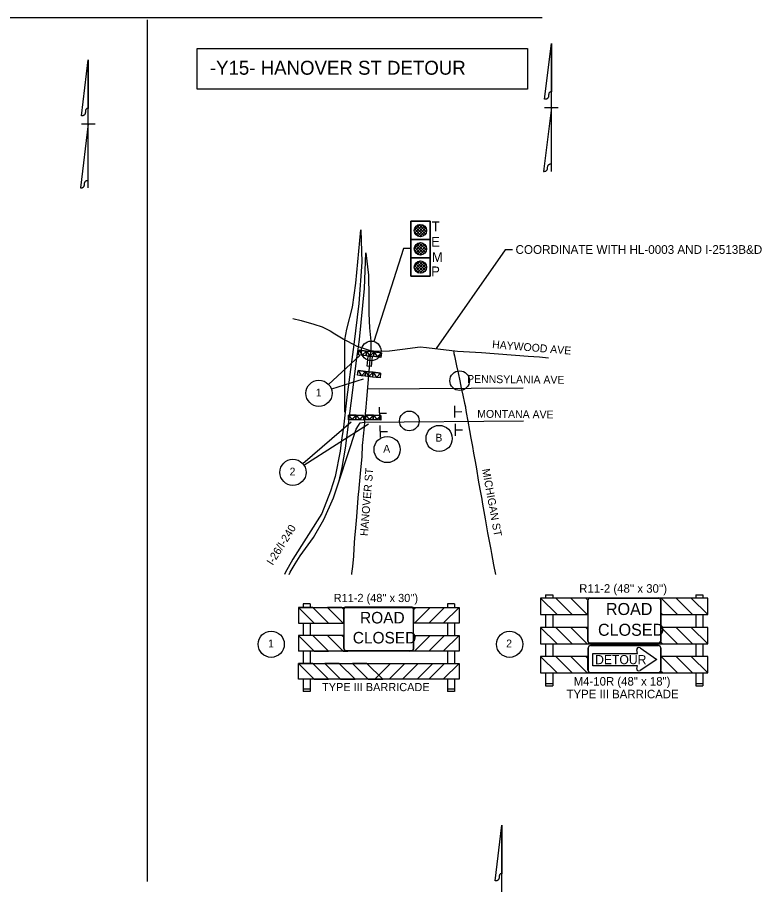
# Model space of a CAD drawing. Extents: x 886234 to 968767, y 455416 to 684046.
# Drawn here: x 915519 to 926197, y 535743 to 548185 of the extents above; entities that cross this region are included whole.
import ezdxf

# ---------------------------------------------------------------- set-up
doc = ezdxf.new("R2010")
doc.units = 0
for name, color, linetype in [('Scratch_Level_3', 7, 'Continuous'), ('TC CONSTRUCTION PROPOSED ROADWAY SHADE', 7, 'Continuous'), ('TC DEV BARRICADE', 7, 'Continuous'), ('TC DEV SIGN', 7, 'Continuous'), ('TC DEV SIGN BLACK 239', 7, 'Continuous'), ('TC DEV SIGN BLACK ZERO', 7, 'Continuous'), ('TC DEV SIGN ORANGE', 7, 'Continuous'), ('TC DEV SIGN WHITE', 7, 'Continuous'), ('TC DEV SIGNAL', 7, 'Continuous'), ('TC LABEL TEXT', 7, 'Continuous'), ('TC SHEET LAYOUT SHAPE', 7, 'Continuous')]:
    doc.layers.add(name, color=color, linetype=linetype)

msp = doc.modelspace()

# ---------------------------------------------------------------- linework, layer by layer
at = {"layer": 'Scratch_Level_3'}
msp.add_line((904674, 548185), (923047, 548185), dxfattribs=at)
at = {"layer": 'TC CONSTRUCTION PROPOSED ROADWAY SHADE'}
msp.add_lwpolyline([(920538, 543179), (920551, 543323), (920607, 543318), (920595, 543176)], close=True, dxfattribs=at)
at = {"layer": 'TC DEV BARRICADE'}
for p, q in [((920413, 543343), (920421, 543410)), ((920421, 543410), (920468, 543337)), ((920468, 543337), (920528, 543398)), ((920528, 543398), (920521, 543331)), ((920521, 543331), (920528, 543398)), ((920528, 543398), (920575, 543325)), ((920575, 543325), (920636, 543386)), ((920636, 543386), (920628, 543319)), ((920628, 543319), (920636, 543386)), ((920636, 543386), (920683, 543313)), ((920683, 543313), (920743, 543374)), ((920743, 543374), (920735, 543307)), ((920468, 543337), (920413, 543343)), ((920521, 543331), (920468, 543337)), ((920468, 543337), (920468, 543337)), ((920468, 543337), (920468, 543337)), ((920575, 543325), (920521, 543331)), ((920628, 543319), (920575, 543325)), ((920575, 543325), (920575, 543325)), ((920575, 543325), (920575, 543325)), ((920683, 543313), (920628, 543319)), ((920735, 543307), (920683, 543313)), ((920683, 543313), (920683, 543313)), ((920683, 543313), (920683, 543313)), ((920400, 543050), (920407, 543117)), ((920407, 543117), (920454, 543043)), ((920454, 543043), (920514, 543105)), ((920514, 543105), (920507, 543037)), ((920507, 543037), (920514, 543105)), ((920514, 543105), (920561, 543031)), ((920454, 543043), (920400, 543050)), ((920507, 543037), (920454, 543043)), ((920454, 543043), (920454, 543043)), ((920454, 543043), (920454, 543043)), ((920561, 543031), (920507, 543037)), ((920561, 543031), (920622, 543093)), ((920614, 543025), (920561, 543031)), ((920561, 543031), (920561, 543031)), ((920561, 543031), (920561, 543031)), ((920622, 543093), (920614, 543025)), ((920614, 543025), (920622, 543093)), ((920669, 543019), (920614, 543025)), ((920622, 543093), (920669, 543019)), ((920669, 543019), (920729, 543081)), ((920722, 543013), (920669, 543019)), ((920669, 543019), (920669, 543019)), ((920669, 543019), (920669, 543019)), ((920729, 543081), (920722, 543013)), ((920268, 542412), (920270, 542480)), ((920323, 542411), (920268, 542412)), ((920270, 542480), (920323, 542411)), ((920323, 542411), (920378, 542477)), ((920376, 542410), (920323, 542411)), ((920323, 542411), (920323, 542411)), ((920323, 542411), (920323, 542411)), ((920378, 542477), (920376, 542410)), ((920376, 542410), (920378, 542477)), ((920431, 542409), (920376, 542410)), ((920378, 542477), (920431, 542409)), ((920431, 542409), (920486, 542475)), ((920484, 542407), (920431, 542409)), ((920431, 542409), (920431, 542409)), ((920431, 542409), (920431, 542409)), ((920486, 542475), (920484, 542407)), ((920517, 542413), (920519, 542480)), ((920572, 542411), (920517, 542413)), ((920519, 542480), (920572, 542411)), ((920572, 542411), (920627, 542478)), ((920625, 542410), (920572, 542411)), ((920572, 542411), (920572, 542411)), ((920572, 542411), (920572, 542411)), ((920627, 542478), (920625, 542410)), ((920625, 542410), (920627, 542478)), ((920680, 542409), (920625, 542410)), ((920627, 542478), (920680, 542409)), ((920680, 542409), (920735, 542475)), ((920733, 542408), (920680, 542409)), ((920680, 542409), (920680, 542409)), ((920680, 542409), (920680, 542409)), ((920735, 542475), (920733, 542408)), ((923097, 539903), (923199, 539903)), ((923097, 539903), (923097, 539852)), ((923199, 539903), (923199, 539852)), ((925252, 539903), (925354, 539903)), ((925252, 539903), (925252, 539852)), ((925354, 539903), (925354, 539852)), ((919718, 539770), (919621, 539770)), ((919621, 539770), (919621, 539721)), ((919718, 539770), (919718, 539721)), ((921788, 539770), (921690, 539770)), ((921690, 539770), (921690, 539721)), ((921788, 539770), (921788, 539721)), ((923026, 539852), (923026, 539617)), ((923242, 539852), (923026, 539852)), ((923026, 539852), (923261, 539617)), ((925426, 539852), (923026, 539852)), ((923477, 539617), (923242, 539852)), ((923674, 539852), (923458, 539852)), ((923458, 539852), (923693, 539617)), ((923704, 539822), (923674, 539852)), ((923702, 539617), (923702, 539814)), ((924970, 539852), (924754, 539852)), ((924754, 539852), (924990, 539617)), ((925206, 539617), (924970, 539852)), ((925426, 539852), (925186, 539852)), ((925186, 539852), (925426, 539617)), ((925426, 539617), (925426, 539852)), ((925426, 539617), (925426, 539852)), ((919759, 539721), (919552, 539721)), ((919552, 539721), (919778, 539495)), ((919552, 539721), (919552, 539495)), ((919552, 539721), (921856, 539721)), ((919985, 539495), (919759, 539721)), ((920174, 539721), (919967, 539721)), ((919967, 539721), (920193, 539495)), ((920203, 539692), (920174, 539721)), ((920202, 539495), (920202, 539685)), ((921205, 539692), (921234, 539721)), ((921206, 539495), (921206, 539685)), ((921441, 539721), (921216, 539495)), ((921234, 539721), (921441, 539721)), ((921423, 539495), (921649, 539721)), ((921856, 539721), (921630, 539495)), ((921649, 539721), (921856, 539721)), ((921856, 539721), (921856, 539495)), ((924774, 539617), (924749, 539642)), ((924749, 539642), (924749, 539617)), ((919552, 539495), (920202, 539495)), ((919621, 539495), (919621, 539319)), ((919718, 539495), (919718, 539319)), ((919778, 539495), (919985, 539495)), ((920193, 539495), (920202, 539495)), ((921216, 539495), (921206, 539495)), ((921856, 539495), (921206, 539495)), ((921630, 539495), (921423, 539495)), ((921690, 539495), (921690, 539319)), ((921788, 539495), (921788, 539319)), ((923026, 539617), (923702, 539617)), ((923097, 539617), (923097, 539434)), ((923199, 539617), (923199, 539434)), ((923261, 539617), (923477, 539617)), ((923693, 539617), (923702, 539617)), ((924749, 539617), (925426, 539617)), ((924749, 539617), (924774, 539617)), ((924990, 539617), (925206, 539617)), ((925252, 539617), (925252, 539434)), ((925354, 539617), (925354, 539434)), ((923026, 539434), (923026, 539198)), ((923242, 539434), (923026, 539434)), ((923026, 539434), (923261, 539198)), ((923702, 539434), (923026, 539434)), ((923477, 539198), (923242, 539434)), ((923458, 539434), (923693, 539198)), ((923674, 539434), (923458, 539434)), ((923702, 539405), (923674, 539434)), ((923702, 539236), (923702, 539405)), ((925426, 539434), (924749, 539434)), ((924970, 539434), (924754, 539434)), ((924754, 539434), (924990, 539198)), ((925206, 539198), (924970, 539434)), ((925426, 539434), (925186, 539434)), ((925186, 539434), (925426, 539198)), ((925426, 539198), (925426, 539434)), ((925426, 539198), (925426, 539434)), ((919552, 539319), (919552, 539093)), ((919759, 539319), (919552, 539319)), ((919552, 539319), (919778, 539093)), ((920202, 539319), (919552, 539319)), ((919985, 539093), (919759, 539319)), ((919967, 539319), (920193, 539093)), ((920174, 539319), (919967, 539319)), ((920202, 539292), (920174, 539319)), ((920202, 539130), (920202, 539292)), ((921206, 539292), (921234, 539319)), ((921206, 539319), (921856, 539319)), ((921206, 539130), (921206, 539292)), ((921441, 539319), (921216, 539093)), ((921234, 539319), (921441, 539319)), ((921423, 539093), (921649, 539319)), ((921856, 539319), (921630, 539093)), ((921649, 539319), (921856, 539319)), ((921856, 539319), (921856, 539093)), ((923026, 539198), (925426, 539198)), ((923097, 539198), (923097, 539015)), ((923199, 539198), (923199, 539015)), ((923261, 539198), (923477, 539198)), ((923693, 539198), (923763, 539198)), ((924688, 539198), (924774, 539198)), ((924774, 539198), (924746, 539226)), ((924990, 539198), (925206, 539198)), ((925252, 539198), (925252, 539015)), ((925354, 539198), (925354, 539015)), ((921856, 539093), (919552, 539093)), ((919621, 539093), (919621, 538917)), ((919718, 539093), (919718, 538917)), ((919778, 539093), (919985, 539093)), ((920193, 539093), (920260, 539093)), ((921216, 539093), (921148, 539093)), ((921630, 539093), (921423, 539093)), ((921690, 539093), (921690, 538917)), ((921788, 539093), (921788, 538917)), ((923026, 539015), (923026, 538780)), ((923242, 539015), (923026, 539015)), ((923026, 539015), (923261, 538780)), ((923702, 539015), (923026, 539015)), ((923477, 538780), (923242, 539015)), ((923458, 539015), (923693, 538780)), ((923674, 539015), (923458, 539015)), ((923702, 538986), (923674, 539015)), ((925426, 539015), (924749, 539015)), ((924970, 539015), (924754, 539015)), ((924754, 539015), (924990, 538780)), ((925206, 538780), (924970, 539015)), ((925426, 539015), (925186, 539015)), ((925186, 539015), (925426, 538780)), ((925426, 538780), (925426, 539015)), ((925426, 538780), (925426, 539015)), ((919759, 538917), (919552, 538917)), ((919552, 538917), (919778, 538692)), ((919985, 538692), (919759, 538917)), ((920137, 538917), (919929, 538917)), ((919929, 538917), (920155, 538692)), ((920363, 538691), (920137, 538917)), ((920535, 538917), (920328, 538917)), ((920328, 538917), (920554, 538692)), ((920761, 538692), (920535, 538917)), ((920647, 538692), (920873, 538917)), ((921080, 538917), (920854, 538692)), ((920873, 538917), (921080, 538917)), ((921046, 538691), (921271, 538917)), ((921479, 538917), (921253, 538692)), ((921271, 538917), (921479, 538917)), ((921423, 538692), (921649, 538917)), ((921856, 538917), (921630, 538692)), ((921649, 538917), (921856, 538917)), ((923702, 538818), (923702, 538986)), ((923026, 538780), (925426, 538780)), ((923097, 538780), (923097, 538596)), ((923199, 538780), (923199, 538596)), ((923261, 538780), (923477, 538780)), ((923693, 538780), (923763, 538780)), ((924688, 538780), (924774, 538780)), ((924774, 538780), (924746, 538807)), ((924990, 538780), (925206, 538780)), ((925252, 538780), (925252, 538596)), ((925354, 538780), (925354, 538596)), ((919621, 538692), (919621, 538515)), ((919718, 538692), (919718, 538515)), ((919778, 538692), (919985, 538692)), ((920155, 538692), (920363, 538691)), ((920554, 538692), (920761, 538692)), ((920854, 538692), (920647, 538692)), ((921253, 538692), (921046, 538691)), ((921630, 538692), (921423, 538692)), ((921690, 538692), (921690, 538515)), ((921788, 538692), (921788, 538515)), ((923097, 538627), (923199, 538627)), ((925252, 538627), (925354, 538627)), ((919718, 538545), (919621, 538545)), ((919718, 538515), (919621, 538515)), ((921788, 538545), (921690, 538545)), ((921788, 538515), (921690, 538515)), ((923097, 538596), (923199, 538596)), ((925252, 538596), (925354, 538596))]:
    msp.add_line(p, q, dxfattribs=at)
for points in [[(920413, 543343), (920421, 543410), (920528, 543398), (920521, 543331)], [(920421, 543410), (920468, 543337), (920528, 543398)], [(920521, 543331), (920528, 543398), (920636, 543386), (920628, 543319)], [(920528, 543398), (920575, 543325), (920636, 543386)], [(920628, 543319), (920636, 543386), (920743, 543374), (920735, 543307)], [(920636, 543386), (920683, 543313), (920743, 543374)], [(920400, 543050), (920407, 543117), (920514, 543105), (920507, 543037)], [(920407, 543117), (920454, 543043), (920514, 543105)], [(920507, 543037), (920514, 543105), (920622, 543093), (920614, 543025)], [(920514, 543105), (920561, 543031), (920622, 543093)], [(920614, 543025), (920622, 543093), (920729, 543081), (920722, 543013)], [(920622, 543093), (920669, 543019), (920729, 543081)], [(920268, 542412), (920270, 542480), (920378, 542477), (920376, 542410)], [(920270, 542480), (920323, 542411), (920378, 542477)], [(920376, 542410), (920378, 542477), (920486, 542475), (920484, 542407)], [(920378, 542477), (920431, 542409), (920486, 542475)], [(920517, 542413), (920519, 542480), (920627, 542478), (920625, 542410)], [(920519, 542480), (920572, 542411), (920627, 542478)], [(920625, 542410), (920627, 542478), (920735, 542475), (920733, 542408)], [(920627, 542478), (920680, 542409), (920735, 542475)]]:
    msp.add_lwpolyline(points, close=True, dxfattribs=at)
for points in [[(921269, 538917), (921856, 538917), (921856, 538692), (919552, 538692), (919552, 538917), (920093, 538917)], [(920093, 538917), (921269, 538917)]]:
    msp.add_lwpolyline(points, dxfattribs=at)
for centre, major_axis, start_param, end_param in [((923764, 539814), (-61, 0), 6.074789, 6.283185), ((920260, 539685), (-58.6, 0), 6.074789, 6.283185), ((921148, 539685), (58.6, 0), 6.283185, 6.491582), ((920260, 539130), (58.6, 0), 3.141593, 4.712389), ((921148, 539130), (-58.6, 0), 1.570796, 3.141593), ((923764, 539236), (61, 0), 3.141593, 4.712389), ((924688, 539236), (61, 0), 4.712497, 5.996053), ((923764, 538818), (61, 0), 3.141593, 4.712389), ((924688, 538818), (61, 0), 4.712497, 5.996053)]:
    msp.add_ellipse(centre, major_axis=major_axis, ratio=0.625, start_param=start_param, end_param=end_param, dxfattribs=at)
at = {"layer": 'TC DEV SIGN'}
for p, q in [((921790, 542613), (921792, 542443)), ((920711, 542591), (920713, 542421)), ((920712, 542506), (920817, 542508)), ((921791, 542528), (921896, 542530)), ((920721, 542330), (920723, 542160)), ((920722, 542245), (920827, 542246)), ((921800, 542352), (921802, 542182)), ((921801, 542267), (921906, 542269))]:
    msp.add_line(p, q, dxfattribs=at)
at = {"layer": 'TC DEV SIGN BLACK 239'}
for p, q in [((924722, 539205), (923732, 539205)), ((920227, 539100), (921178, 539100))]:
    msp.add_line(p, q, dxfattribs=at)
for points in [[(923706, 539231), (923706, 539830)], [(923732, 539856), (924722, 539856)], [(924749, 539830), (924749, 539231)], [(920202, 539700), (920202, 539125)], [(921178, 539725), (920227, 539725)], [(921203, 539125), (921203, 539700)]]:
    msp.add_lwpolyline(points, dxfattribs=at)
for centre, radius, start, end in [((923732, 539830), 26.1, 90, 180), ((924722, 539830), 26.1, 0, 90), ((920227, 539700), 25, 90, 180), ((921178, 539700), 25, 360, 90), ((920227, 539125), 25, 180, 269.9991), ((921178, 539125), 25, 269.9991, 0), ((923732, 539231), 26.1, 180, 270.0009), ((924722, 539231), 26.1, 270.0009, 360)]:
    msp.add_arc(centre, radius, start, end, dxfattribs=at)
at = {"layer": 'TC DEV SIGN BLACK ZERO'}
for p, q in [((923708, 539139), (923708, 538814)), ((924718, 539172), (923741, 539172)), ((924455, 539138), (924692, 538971)), ((924750, 538814), (924750, 539139)), ((923774, 538884), (923774, 539060)), ((923774, 539060), (924416, 539060)), ((924416, 539060), (924405, 539111)), ((924415, 538884), (923774, 538884)), ((924405, 538842), (924415, 538884)), ((924692, 538971), (924455, 538815)), ((923741, 538781), (924718, 538781))]:
    msp.add_line(p, q, dxfattribs=at)
for points in [[(923708, 538814), (923708, 539139)], [(923741, 539172), (924718, 539172)], [(924750, 539139), (924750, 538814)], [(924718, 538781), (923741, 538781)]]:
    msp.add_lwpolyline(points, dxfattribs=at)
for centre, start, end in [((923741, 539139), 90, 180), ((923741, 539139), 90, 180), ((924718, 539139), 360, 90), ((924718, 539139), 360, 90), ((923741, 538814), 180, 270), ((923741, 538814), 180, 270), ((924718, 538814), 270, 0), ((924718, 538814), 270, 360)]:
    msp.add_arc(centre, 32.6, start, end, dxfattribs=at)
for centre, start_param, end_param in [((924436, 539119), 0.96961, 3.452569), ((924436, 538834), 2.830617, 5.313577)]:
    msp.add_ellipse(centre, major_axis=(33, 0), ratio=0.720018, start_param=start_param, end_param=end_param, dxfattribs=at)
at = {"layer": 'TC DEV SIGN ORANGE'}
for p, q in [((924455, 539138), (924692, 538971)), ((923774, 538884), (923774, 539060)), ((923774, 539060), (924416, 539060)), ((924416, 539060), (924405, 539111)), ((924415, 538884), (923774, 538884)), ((924405, 538842), (924415, 538884)), ((924692, 538971), (924455, 538815))]:
    msp.add_line(p, q, dxfattribs=at)
for centre, start_param, end_param in [((924436, 539119), 0.96961, 3.452569), ((924436, 538834), 2.830617, 5.313577)]:
    msp.add_ellipse(centre, major_axis=(33, 0), ratio=0.720018, start_param=start_param, end_param=end_param, dxfattribs=at)
at = {"layer": 'TC DEV SIGN WHITE'}
for p, q in [((924722, 539208), (923732, 539208)), ((920227, 539103), (921178, 539103))]:
    msp.add_line(p, q, dxfattribs=at)
for points in [[(923710, 539231), (923710, 539830)], [(923732, 539853), (924722, 539853)], [(924745, 539830), (924745, 539231)], [(920205, 539700), (920205, 539125)], [(921178, 539722), (920227, 539722)], [(921200, 539125), (921200, 539700)]]:
    msp.add_lwpolyline(points, dxfattribs=at)
for centre, radius, start, end in [((923732, 539830), 22.8, 90, 180), ((924722, 539830), 22.8, 0, 90), ((920227, 539700), 21.9, 90, 180), ((921178, 539700), 21.9, 360, 90), ((920227, 539125), 21.9, 180, 269.9991), ((921178, 539125), 21.9, 269.9991, 0), ((923732, 539231), 22.8, 180, 270.0009), ((924722, 539231), 22.8, 270.0009, 360)]:
    msp.add_arc(centre, radius, start, end, dxfattribs=at)
at = {"layer": 'TC DEV SIGNAL'}
for p, q in [((921213, 545128), (921299, 545214)), ((921283, 545039), (921215, 545108)), ((921324, 545041), (921216, 545149)), ((921220, 545092), (921335, 545208)), ((921353, 545055), (921230, 545177)), ((921236, 545066), (921361, 545191)), ((921374, 545076), (921251, 545199)), ((921260, 545048), (921379, 545166)), ((921387, 545105), (921280, 545212)), ((921293, 545039), (921389, 545134)), ((921386, 545148), (921324, 545211)), ((921351, 545054), (921376, 545079)), ((921213, 544866), (921299, 544952)), ((921283, 544777), (921215, 544846)), ((921324, 544779), (921216, 544887)), ((921220, 544830), (921335, 544946)), ((921353, 544793), (921230, 544915)), ((921236, 544804), (921361, 544929)), ((921374, 544814), (921251, 544937)), ((921260, 544786), (921379, 544904)), ((921387, 544843), (921280, 544950)), ((921293, 544777), (921389, 544872)), ((921386, 544886), (921324, 544949)), ((921351, 544792), (921376, 544817)), ((921213, 544604), (921299, 544690)), ((921324, 544517), (921216, 544625)), ((921220, 544568), (921335, 544684)), ((921353, 544531), (921230, 544653)), ((921236, 544542), (921361, 544667)), ((921374, 544552), (921251, 544675)), ((921260, 544524), (921379, 544642)), ((921387, 544581), (921280, 544688)), ((921293, 544515), (921389, 544610)), ((921386, 544624), (921324, 544687)), ((921283, 544515), (921215, 544584)), ((921351, 544530), (921376, 544555))]:
    msp.add_line(p, q, dxfattribs=at)
for points in [[(921163, 545260), (921439, 545260), (921439, 544474), (921163, 544474)], [(921163, 544998), (921439, 544998), (921439, 545260), (921163, 545260)], [(921163, 544736), (921439, 544736), (921439, 544998), (921163, 544998)], [(921163, 544474), (921439, 544474), (921439, 544736), (921163, 544736)]]:
    msp.add_lwpolyline(points, close=True, dxfattribs=at)
for centre in [(921301, 545126), (921301, 544864), (921301, 544602)]:
    msp.add_circle(centre, 88.8, dxfattribs=at)
at = {"layer": 'TC LABEL TEXT'}
for p, q in [((917380, 548148), (917380, 535787)), ((919984, 542920), (920430, 543333)), ((920468, 543337), (920468, 543336)), ((920482, 542996), (920025, 542849)), ((920540, 542856), (922777, 542871)), ((920308, 542378), (919615, 541781)), ((920500, 542380), (922780, 542396)), ((919631, 541759), (920559, 542352))]:
    msp.add_line(p, q, dxfattribs=at)
msp.add_lwpolyline([(918098, 547740), (922837, 547740), (922837, 547157), (918098, 547157)], close=True, dxfattribs=at)
for points in [[(920216, 543561), (920246, 543714), (920328, 544026), (920376, 544374), (920446, 545139)], [(920446, 545139), (920461, 544675), (920417, 544079), (920346, 543490)], [(921163, 544867), (921057, 544867), (920634, 543535)], [(922623, 544852), (922517, 544852), (921528, 543433)], [(920414, 543457), (920426, 543566), (920499, 544293), (920520, 544807)], [(920520, 544807), (920558, 544488), (920562, 544178), (920562, 543936), (920571, 543733), (920588, 543538), (920592, 543402)], [(919472, 543864), (919589, 543837), (919773, 543785), (919890, 543747), (920009, 543690), (920074, 543646), (920170, 543588), (920227, 543552), (920346, 543490)], [(920346, 543490), (920329, 543347), (920246, 542735), (920199, 542305), (920163, 542093), (920148, 541964), (920077, 541596), (920010, 541390), (919886, 541068)], [(920216, 542519), (920216, 543301), (920216, 543413), (920216, 543561)], [(920346, 543490), (920380, 543474), (920414, 543457)], [(919417, 540194), (919435, 540228), (919503, 540347), (919576, 540460), (919768, 540724), (919917, 540982), (920054, 541291), (920136, 541538), (920179, 541725), (920226, 542003), (920389, 543297), (920414, 543457)], [(923138, 543297), (923010, 543308), (922846, 543321), (922178, 543371), (921832, 543391), (921387, 543444), (921296, 543456), (921044, 543418), (920857, 543394), (920671, 543392), (920584, 543400), (920414, 543457)], [(920585, 543390), (920527, 542706)], [(921775, 543398), (921779, 543376), (921782, 543364), (921788, 543328), (921821, 543186), (921845, 543087), (921865, 542973), (921887, 542867), (921911, 542763), (921935, 542652), (921948, 542596), (921949, 542583)], [(920527, 542706), (920518, 542593), (920505, 542447), (920494, 542312), (920478, 542176), (920469, 542082), (920467, 542048)], [(921949, 542583), (921959, 542518), (921984, 542390), (922004, 542260), (922025, 542149), (922047, 542028), (922063, 541933), (922068, 541909)], [(920136, 541538), (920381, 542276), (920411, 542332), (920437, 542368), (920500, 542380)], [(920467, 542048), (920459, 541881), (920441, 541695), (920436, 541640), (920421, 541484), (920412, 541375)], [(922068, 541909), (922086, 541812), (922104, 541710), (922131, 541548), (922155, 541415), (922181, 541271), (922188, 541232)], [(920412, 541375), (920410, 541348), (920401, 541223), (920386, 541020), (920365, 540809), (920358, 540719)], [(922188, 541232), (922203, 541147), (922230, 540993), (922248, 540878), (922266, 540791), (922310, 540550)], [(919886, 541068), (919472, 540412), (919362, 540215), (919351, 540194)], [(920358, 540719), (920353, 540645), (920341, 540466)], [(922310, 540550), (922320, 540496), (922352, 540331), (922377, 540194)], [(920341, 540466), (920340, 540453), (920327, 540309), (920315, 540205), (920314, 540194)]]:
    msp.add_lwpolyline(points, dxfattribs=at)
for centre, radius in [((920595, 543400), 141), ((921865, 542973), 141), ((921865, 542973), 141), ((919846, 542792), 188), ((921142, 542395), 141), ((921142, 542395), 141), ((921570, 542144), 188), ((920824, 541985), 188), ((919473, 541658), 188), ((919161, 539192), 188), ((922581, 539192), 188)]:
    msp.add_circle(centre, radius, dxfattribs=at)
at = {"layer": 'TC SHEET LAYOUT SHAPE'}
for p, q in [((923083, 547011), (923181, 547812)), ((923083, 547011), (923181, 547812)), ((923181, 545976), (923181, 547812)), ((923181, 547812), (923181, 547115)), ((923181, 547812), (923181, 547115)), ((916437, 546773), (916536, 547575)), ((916437, 546773), (916536, 547575)), ((916536, 545738), (916536, 547575)), ((916536, 547575), (916536, 546877)), ((916536, 547575), (916536, 546877)), ((923181, 546894), (923068, 545976)), ((923083, 546894), (923279, 546894)), ((923181, 546084), (923181, 546894)), ((916536, 546657), (916423, 545738)), ((916437, 546657), (916634, 546657)), ((916535, 545847), (916536, 546657)), ((922372, 535796), (922471, 536597)), ((922372, 535796), (922471, 536597)), ((922471, 534761), (922471, 536597)), ((922471, 536597), (922471, 535900)), ((922471, 536597), (922471, 535900))]:
    msp.add_line(p, q, dxfattribs=at)
for points in [[(923181, 547115), (923141, 547120), (923140, 547008), (923083, 547011)], [(923181, 547115), (923141, 547120), (923140, 547008), (923083, 547011)], [(916536, 546877), (916496, 546883), (916494, 546770), (916437, 546773)], [(916536, 546877), (916496, 546883), (916494, 546770), (916437, 546773)], [(923068, 545976), (923125, 545973), (923127, 546085), (923181, 546084)], [(916423, 545738), (916480, 545735), (916482, 545848), (916535, 545847)], [(922471, 535900), (922431, 535905), (922429, 535793), (922372, 535796)], [(922471, 535900), (922431, 535905), (922429, 535793), (922372, 535796)]]:
    msp.add_open_spline(points, degree=2, dxfattribs=at)

# ---------------------------------------------------------------- texts
at = {"layer": 'TC DEV BARRICADE'}
for s, height, p in [("R11-2 (48'' x 30'')", 122.24, (923579, 539931)), ("R11-2 (48'' x 30'')", 117.35, (920058, 539797)), ('TYPE III BARRICADE', 117.35, (919890, 538519)), ('M4-10R (48" x 18")', 122.24, (923500, 538599)), ('TYPE III BARRICADE', 122.24, (923398, 538416))]:
    msp.add_text(s, height=height, dxfattribs=at).set_placement(p)
at = {"layer": 'TC DEV SIGN BLACK 239'}
for s, p in [('ROAD', (923963, 539611)), ('CLOSED', (923849, 539313))]:
    msp.add_text(s, height=172.6, rotation=360, dxfattribs=at).set_placement(p)
for s, p in [('ROAD', (920435, 539490)), ('CLOSED', (920331, 539203))]:
    msp.add_text(s, height=165.7, dxfattribs=at).set_placement(p)
at = {"layer": 'TC DEV SIGN BLACK ZERO'}
msp.add_text('DETOUR', height=130.3, dxfattribs=at).set_placement((923808, 538906))
at = {"layer": 'TC DEV SIGNAL'}
for s, p in [('T', (921464, 545117)), ('E', (921455, 544896)), ('M', (921466, 544675)), ('P', (921456, 544471))]:
    msp.add_text(s, height=140, rotation=359.9999, dxfattribs=at).set_placement(p)
at = {"layer": 'TC LABEL TEXT'}
for s, height, p in [('-Y15- HANOVER ST DETOUR', 200, (918281, 547362)), ('COORDINATE WITH HL-0003 AND I-2513B&D', 125, (922666, 544792)), ('1', 112, (919801, 542747)), ('B', 112, (921516, 542099)), ('A', 112, (920768, 541940)), ('2', 112, (919425, 541613)), ('1', 112, (919116, 539147)), ('2', 112, (922532, 539147))]:
    msp.add_text(s, height=height, dxfattribs=at).set_placement(p)
for s, rotation, p in [('HAYWOOD AVE', 355.2398, (922327, 543441)), ('PENNSYLANIA AVE', 359.4473, (921971, 542942)), ('MONTANA AVE', 359.4473, (922116, 542442)), ('HANOVER ST', 85.2418, (920545, 540741)), ('MICHIGAN ST', 280.3462, (922185, 541701)), ('I-26/I-240', 58.0765, (919182, 540316))]:
    msp.add_text(s, height=112.5, rotation=rotation, dxfattribs=at).set_placement(p)

doc.saveas('drawing.dxf')
